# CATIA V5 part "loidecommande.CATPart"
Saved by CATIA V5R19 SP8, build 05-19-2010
Part number: loidecommande
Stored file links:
  G:\EU_thinkMotion\CFAO_2010\MMS_groupe2\MMS_groupe2\OK\mmartini\mmartiniCFAO\loidecommande.CATPart

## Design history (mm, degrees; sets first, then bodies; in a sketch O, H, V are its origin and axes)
AxisSystem1: origin (0, 0, 0), X (1, 0, 0), Y (0, 1, 0), Z (0, 0, 1)
Set1
  Sketch1 "supportcanon" on YZ plane of AxisSystem1, origin (0, 0, 0), H (0, 1, 0), V (0, 0, 1)
    line L1 (0, 0) -> (477.157, 20)
    point P1 (477.157, 20)
    line L2 (477.157, 20) -> (1062.0124, -20)
    point P2 (1062.0124, -20)
    line L3 (1062.0124, -20) -> (1460.1903, 0)
    point P3 (1460.1903, 0)
    axis line L4 (0, 0) -> (3190.1275, 0)
    point P4 (0, 0)
    distance L4 P1 = 20
    distance P2 L4 = 20
    coincidence: P4 L1, P4 H, P3 L4
    horizontal: L4 H
  Sketch2 on YZ plane of AxisSystem1, origin (0, 0, 0), H (0, 1, 0), V (0, 0, 1)
    line L1 (0, 0) -> (84.5695, 308.321)
    point P1 (84.5695, 308.321)
    construction line L2 (0, 0) -> (2272.6328, 0)
    line L3 (84.5695, 308.321) -> (179.0166, 0)
    point P3 (179.0166, 0)
    line L4 (179.0166, 0) -> (303.0433, 313.9218)
    point P4 (303.0433, 313.9218)
    line L5 (303.0433, 313.9218) -> (419.6739, 0)
    point P5 (419.6739, 0)
    line L6 (419.6739, 0) -> (522.2155, 314.1214)
    point P6 (522.2155, 314.1214)
    line L7 (522.2155, 314.1214) -> (638.8589, 0)
    point P7 (638.8589, 0)
    axis line L8 (638.8589, 0) -> (638.8589, 411.0814)
    point P9 (638.8589, 0)
    point P10 (755.5024, 314.1214)
    line L9 (755.5024, 314.1214) -> (638.8589, 0)
    point P11 (858.0439, 0)
    line L10 (858.0439, 0) -> (755.5024, 314.1214)
    point P12 (974.6746, 313.9218)
    line L11 (974.6746, 313.9218) -> (858.0439, 0)
    point P13 (1098.7013, 0)
    line L12 (1098.7013, 0) -> (974.6746, 313.9218)
    point P14 (1193.1484, 308.321)
    line L13 (1193.1484, 308.321) -> (1098.7013, 0)
    point P15 (1277.7178, 0)
    line L14 (1277.7178, 0) -> (1193.1484, 308.321)
    coincidence: P3 L2, P5 L2, P7 L2
    horizontal: L2 H
    vertical: L8 V
    symmetry: P7 P9 L8, P6 P10 L8, L7 L9 L8, P5 P11 L8, L6 L10 L8, P4 P12 L8, L5 L11 L8, P3 P13 L8, L4 L12 L8, P1 P14 L8, L3 L13 L8, O P15 L8, L1 L14 L8
  LawDistProj1: Reference Sketch1.H, Definition Sketch1, LawScaling 1
  LawDistProj2: Reference Sketch2.H, Definition Sketch2, LawScaling 1
  LawDistProj3: Reference Sketch1.H, Definition Sketch1, LawScaling 1
  Sketch3 on YZ plane of AxisSystem1, origin (0, 0, 0), H (0, 1, 0), V (0, 0, 1)
    line L1 (0, 0) -> (643.1843, 200)
    point P1 (643.1843, 200)
    line L2 (643.1843, 200) -> (1228.9437, 0)
    point P2 (643.1843, 200)
    point P3 (1228.9437, 0)
    distance P1 O V = 200
    coincidence: P2 L1, P3 H
  LawDistProj4: Reference Sketch3.H, Definition Sketch3, LawScaling 1
  Sketch4 on YZ plane of AxisSystem1, origin (0, 0, 0), H (0, 1, 0), V (0, 0, 1)
    line L1 (0, 0) -> (643.1843, 14)
    point P1 (643.1843, 14)
    axis line L2 (643.1843, 330.9752) -> (643.1843, -126.6753)
    reference projected point E1 (643.1843, 200) from vertex [element of Sketch3 | element of Sketch3]
    line L3 (643.1843, 14) -> (1228.9437, 0)
    point P4 (1228.9437, 0)
    reference projected point E2 (1228.9437, 0) from Sketch3.P3
    distance O P1 V = 14
    vertical: L2 V
    coincidence: L2 E1, P1 L2, P4 H, P4 E2
  LawDistProj5: Reference Sketch3.H, Definition Sketch3, LawScaling 1
  LawDistProj6: Reference Sketch4.H, Definition Sketch4, LawScaling 1
  Sketch5 on YZ plane of AxisSystem1, origin (0, 0, 0), H (0, 1, 0), V (0, 0, 1)
    line L1 (0, 0) -> (234.724, 10)
    point P1 (234.724, 10)
    line L2 (234.724, 10) -> (490.4985, 0)
    point P2 (490.4985, 0)
    line L3 (490.4985, 0) -> (2659.2208, 0)
    distance P1 P2 V = 10
    coincidence: P2 H
    horizontal: L3 H
  LawDistProj7: Reference Sketch5.H, Definition Sketch5, LawScaling 1
  Sketch6 on YZ plane of AxisSystem1, origin (0, 0, 0), H (0, 1, 0), V (0, 0, 1)
    line L1 (0, 0) -> (244.1409, -10)
    point P1 (244.1409, -10)
    line L2 (244.1409, -10) -> (463.711, 0)
    point P2 (244.1409, -10)
    point P3 (463.711, 0)
    line L3 (463.711, 0) -> (2669.8824, 0)
    point P4 (463.711, 0)
    distance P1 L3 = 10
    coincidence: P2 L1, P3 H, P4 L2, P4 H, P1 P2
    horizontal: L3 H
  LawDistProj8: Reference Sketch6.H, Definition Sketch6, LawScaling 1
  Sketch7 on YZ plane of AxisSystem1, origin (0, 0, 0), H (0, 1, 0), V (0, 0, 1)
    line L1 (0, 0) -> (88.4429, -10)
    point P1 (88.4429, -10)
    line L2 (88.4429, -10) -> (170.319, 0)
    point P2 (88.4429, -10)
    point P3 (170.319, 0)
    line L3 (170.319, 0) -> (2669.8824, 0)
    point P4 (170.319, 0)
    distance P1 L3 = 10
    coincidence: P2 L1, P3 H, P4 L2, P4 H
    horizontal: L3 H
Body1 (main body)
